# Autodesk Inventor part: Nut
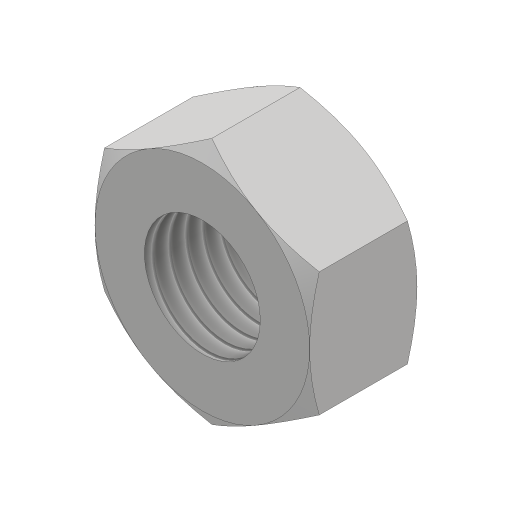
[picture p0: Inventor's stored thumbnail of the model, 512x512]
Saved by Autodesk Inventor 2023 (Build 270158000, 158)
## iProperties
Created: 2016-05
Part Number: Nut
Material: Generic
Document SubType Name: Modeling
Designer: CADCIM
Density: 1 g/cm^3
Appearance: Default
Author: CADCIM
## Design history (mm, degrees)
sketch "Sketch1"
  geometry: L1 (0, -18.475)-(-16, -9.238); L2 (-16, -9.238)-(-16, 9.238); L3 (-16, 9.238)-(0, 18.475); L4 (0, 18.475)-(16, 9.238); L5 (16, 9.238)-(16, -9.238); L6 (16, -9.238)-(0, -18.475); 2 further points
  constraints: 12 end point, 1 coincident, 13 other
  dimensions: "d0" = 32 distance between parallel lines of L2 L5
extrude "Extrusion1" new body sketch "Sketch1" distance "d1" = 16; taper "d2" = 0 deg
sketch "Sketch2"
  geometry: L1 (16, -9.238)-(16, 9.238) reference; C1 r 16 at (0, 0); 1 further point
  constraints: 1 centre point, 1 coincident, 1 tangent
extrude "Extrusion2" sketch "Sketch2" distance "d3" = 16; taper "d4" = 60 deg
sketch "Sketch3"
  geometry: L1 (0, -18.475)-(16, -9.238) reference; C1 r 16 at (0, 0); 1 further point
  constraints: 1 centre point, 1 coincident, 1 tangent
extrude "Extrusion3" sketch "Sketch3" distance "d5" = 16; taper "d6" = 60 deg
hole "Hole1" diameter "d9" = 17.294; stored, may be unused: countersink angle "d13" = 90 deg, drill point angle "d15" = 118 deg; dims "d7" = 10, "d8" = 10, "d10" = 40, "d11" = 4, "d12" = 2, "d14" = 51.2
body "Solid1"
